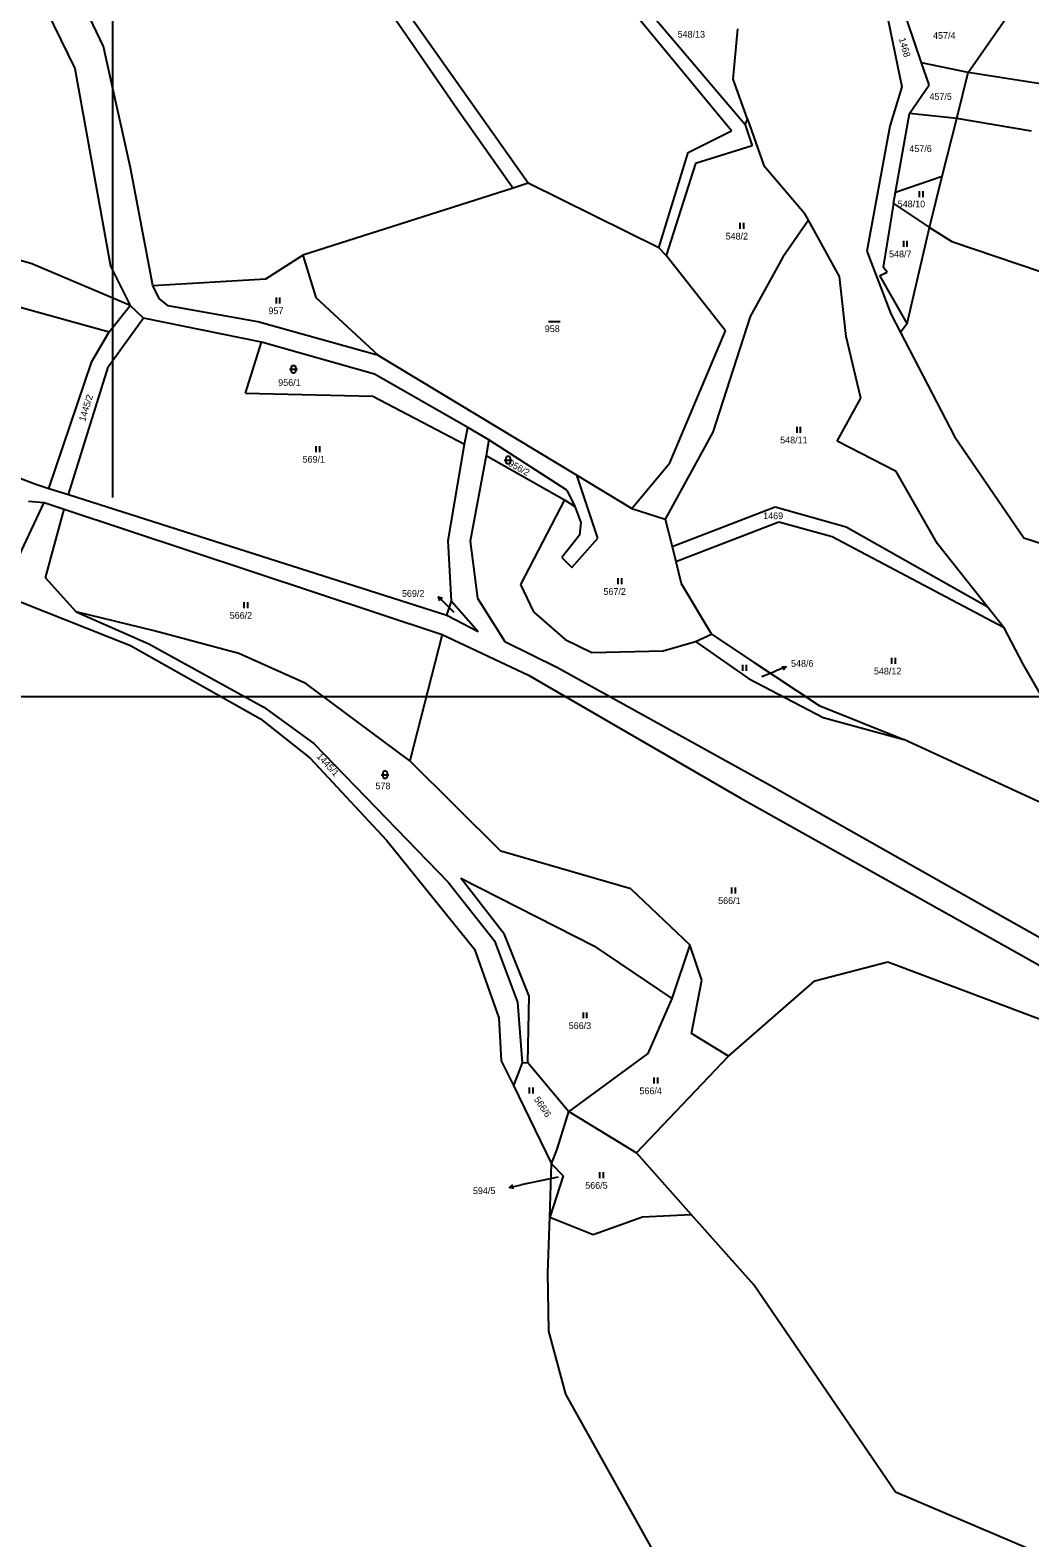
# Model space of a CAD drawing. Extents: x -852001 to -842497, y -1063614 to -1052182.
# Drawn here: x -848771 to -848517.5, y -1057263.9 to -1056881.4 of the extents above; entities that cross this region are included whole.
import ezdxf

# ---------------------------------------------------------------- set-up
doc = ezdxf.new("R2010")
doc.units = 0
for name, color, linetype in [('Default', 7, 'Continuous'), ('KLADY_ZMVM', 7, 'Continuous'), ('KN_HRANICE', 7, 'Continuous'), ('KN_KULTURY', 7, 'Continuous'), ('KN_PARCELY', 7, 'Continuous'), ('LEGENDA', 7, 'Continuous')]:
    doc.layers.add(name, color=color, linetype=linetype)

# ---------------------------------------------------------------- blocks, each defined once
blk = doc.blocks.new('306')
at = {"layer": 'Default'}
for p, q in [((-0.5, 1.5), (-0.5, 0)), ((0.5, 0), (0.5, 1.5))]:
    blk.add_line(p, q, dxfattribs=at)
blk = doc.blocks.new('316')
at = {"layer": 'Default'}
for points in [[(-1, 1), (0.27, 1), (1, 1)], [(-0.5, 1.5), (-0.4, 1.79), (-0.15, 1.97), (0.16, 1.97), (0.41, 1.79), (0.51, 1.5), (0.51, 0.5), (0.41, 0.21), (0.16, 0.03), (-0.15, 0.03), (-0.4, 0.21), (-0.5, 0.5), (-0.5, 1.5)]]:
    blk.add_lwpolyline(points, dxfattribs=at)
blk = doc.blocks.new('804')
at = {"layer": 'Default'}
blk.add_line((-1.5, 0), (1.5, 0), dxfattribs=at)
blk = doc.blocks.new('10292')
at = {"layer": 'Default'}
blk.add_line((0, 3), (0, 0), dxfattribs=at)
blk.add_lwpolyline([(-0.5, 2), (0, 3), (0.5, 2)], dxfattribs=at)

msp = doc.modelspace()

# ---------------------------------------------------------------- linework, layer by layer
at = {"layer": 'KLADY_ZMVM'}
msp.add_line((-848750, -1057000), (-848750, -1056500), dxfattribs=at)
at = {"layer": 'KN_HRANICE'}
for p, q in [((-848828.18, -1056749.16), (-848759.71, -1056891.14)), ((-848752.4, -1056885.52), (-848803.86, -1056777.8)), ((-848644.67, -1056920.2), (-848707.81, -1056830.91)), ((-848593.1, -1056906.95), (-848656.48, -1056830.13)), ((-848709.93, -1056832.61), (-848662.72, -1056901.35)), ((-848589.7, -1056905.37), (-848643.92, -1056841.44)), ((-848554.75, -1056872.56), (-848549.94, -1056895.74)), ((-848533.12, -1056892.09), (-848522.36, -1056876.75)), ((-848592.71, -1056893.78), (-848591.54, -1056881.04)), ((-848544.95, -1056889.68), (-848548.59, -1056878.97)), ((-848745.51, -1056916.29), (-848752.4, -1056885.52)), ((-848759.71, -1056891.14), (-848750.65, -1056941.27)), ((-848543.05, -1056895.26), (-848544.95, -1056889.68)), ((-848533.12, -1056892.09), (-848544.95, -1056889.68)), ((-848536, -1056903.82), (-848533.12, -1056892.09)), ((-848510.51, -1056895.7), (-848533.12, -1056892.09)), ((-848589.08, -1056904.01), (-848592.71, -1056893.78)), ((-848549.94, -1056895.74), (-848553, -1056905.72)), ((-848548.04, -1056902.53), (-848543.05, -1056895.26)), ((-848662.72, -1056901.35), (-848648.49, -1056921.48)), ((-848589.7, -1056905.37), (-848589.08, -1056904.01)), ((-848589.08, -1056904.01), (-848584.95, -1056915.69)), ((-848551.59, -1056922.52), (-848548.04, -1056902.53)), ((-848536, -1056903.82), (-848548.04, -1056902.53)), ((-848539.72, -1056918.46), (-848536, -1056903.82)), ((-848517.02, -1056907.05), (-848536, -1056903.82)), ((-848604.13, -1056912.41), (-848593.1, -1056906.95)), ((-848589.7, -1056905.37), (-848587.93, -1056910.75)), ((-848553, -1056905.72), (-848558.86, -1056937.48)), ((-848587.93, -1056910.75), (-848602.23, -1056915.24)), ((-848611.55, -1056936.6), (-848604.13, -1056912.41)), ((-848602.23, -1056915.24), (-848609.69, -1056938.54)), ((-848584.95, -1056915.69), (-848574.65, -1056927.8)), ((-848739.87, -1056946.18), (-848745.51, -1056916.29)), ((-848551.59, -1056922.52), (-848539.72, -1056918.46)), ((-848542.97, -1056931.46), (-848539.72, -1056918.46)), ((-848648.49, -1056921.48), (-848701.82, -1056938.46)), ((-848644.67, -1056920.2), (-848648.49, -1056921.48)), ((-848611.55, -1056936.6), (-848644.67, -1056920.2)), ((-848552.02, -1056925.36), (-848551.59, -1056922.52)), ((-848552.02, -1056925.36), (-848554.64, -1056941.54)), ((-848552.02, -1056925.36), (-848542.97, -1056931.46)), ((-848573.65, -1056929.62), (-848580.15, -1056938.95)), ((-848573.65, -1056929.62), (-848574.65, -1056927.8)), ((-848565.78, -1056943.93), (-848573.65, -1056929.62)), ((-848548.58, -1056955.83), (-848542.97, -1056931.46)), ((-848542.97, -1056931.46), (-848537.27, -1056935.01)), ((-848537.27, -1056935.01), (-848500.98, -1056947.31)), ((-848770.6, -1056940.69), (-848784.91, -1056936.55)), ((-848711.24, -1056944.47), (-848701.82, -1056938.46)), ((-848701.82, -1056938.46), (-848698.56, -1056949.2)), ((-848609.69, -1056938.54), (-848611.55, -1056936.6)), ((-848594.67, -1056957.65), (-848609.69, -1056938.54)), ((-848558.86, -1056937.48), (-848552.74, -1056953.4)), ((-848745.67, -1056951.27), (-848770.6, -1056940.69)), ((-848750.65, -1056941.27), (-848745.67, -1056951.27)), ((-848580.15, -1056938.95), (-848588.38, -1056954.07)), ((-848553.69, -1056942.78), (-848554.64, -1056941.54)), ((-848798.55, -1056944.74), (-848750.93, -1056957.95)), ((-848739.87, -1056946.18), (-848711.24, -1056944.47)), ((-848738.3, -1056949.45), (-848739.87, -1056946.18)), ((-848564.06, -1056959.08), (-848565.78, -1056943.93)), ((-848555.53, -1056943.66), (-848553.69, -1056942.78)), ((-848548.58, -1056955.83), (-848555.53, -1056943.66)), ((-848735.99, -1056951.35), (-848738.3, -1056949.45)), ((-848698.56, -1056949.2), (-848682.69, -1056963.91)), ((-848750.93, -1056957.95), (-848745.67, -1056951.27)), ((-848742.29, -1056954.46), (-848745.67, -1056951.27)), ((-848713.26, -1056955.43), (-848735.99, -1056951.35)), ((-848588.38, -1056954.07), (-848597.91, -1056983.38)), ((-848552.74, -1056953.4), (-848550.28, -1056958.12)), ((-848755.32, -1056965.44), (-848750.93, -1056957.95)), ((-848742.29, -1056954.46), (-848751.21, -1056966.93)), ((-848712.37, -1056960.52), (-848742.29, -1056954.46)), ((-848682.69, -1056963.91), (-848713.26, -1056955.43)), ((-848608.75, -1056991.15), (-848594.67, -1056957.65)), ((-848548.58, -1056955.83), (-848550.28, -1056958.12)), ((-848716.35, -1056973.49), (-848712.37, -1056960.52)), ((-848683.64, -1056968.67), (-848712.37, -1056960.52)), ((-848560.31, -1056974.75), (-848564.06, -1056959.08)), ((-848550.28, -1056958.12), (-848536.56, -1056984.46)), ((-848766.22, -1056997.65), (-848755.32, -1056965.44)), ((-848682.69, -1056963.91), (-848632.4, -1056994.3)), ((-848761.29, -1056999.22), (-848751.21, -1056966.93)), ((-848660.01, -1056982.18), (-848683.64, -1056968.67)), ((-848716.35, -1056973.49), (-848684.09, -1056974.22)), ((-848684.09, -1056974.22), (-848660.81, -1056986.46)), ((-848566.34, -1056985.65), (-848560.31, -1056974.75)), ((-848660.81, -1056986.46), (-848660.01, -1056982.18)), ((-848654.7, -1056985.34), (-848660.01, -1056982.18)), ((-848597.91, -1056983.38), (-848609.93, -1057005.5)), ((-848536.56, -1056984.46), (-848518.98, -1057010.18)), ((-848794.78, -1056987.07), (-848769.55, -1056996.59)), ((-848665, -1057010.87), (-848660.81, -1056986.46)), ((-848654.7, -1056985.34), (-848655.36, -1056989.32)), ((-848634.94, -1056998.1), (-848654.7, -1056985.34)), ((-848551.36, -1056993.36), (-848566.34, -1056985.65)), ((-848655.36, -1056989.32), (-848659.41, -1057011.08)), ((-848655.36, -1056989.32), (-848635.5, -1057000.56)), ((-848618.39, -1057002.77), (-848608.75, -1056991.15)), ((-848627, -1057010.3), (-848632.4, -1056994.3)), ((-848632.4, -1056994.3), (-848618.39, -1057002.77)), ((-848540.94, -1057011.71), (-848551.36, -1056993.36)), ((-848769.55, -1056996.59), (-848766.22, -1056997.65)), ((-848766.22, -1056997.65), (-848761.29, -1056999.22)), ((-848761.29, -1056999.22), (-848665.36, -1057029.84)), ((-848634.94, -1056998.1), (-848632.88, -1057002.25)), ((-848778.33, -1057024.53), (-848767.43, -1057001.23)), ((-848771.39, -1057000.87), (-848767.43, -1057001.23)), ((-848767.43, -1057001.23), (-848762.41, -1057002.9)), ((-848767.14, -1057020.35), (-848762.41, -1057002.9)), ((-848762.41, -1057002.9), (-848666.55, -1057034.72)), ((-848635.5, -1057000.56), (-848646.62, -1057022.01)), ((-848635.5, -1057000.56), (-848632.88, -1057002.25)), ((-848632.88, -1057002.25), (-848631.39, -1057006.3)), ((-848618.39, -1057002.77), (-848609.93, -1057005.5)), ((-848608.2, -1057012.41), (-848582.08, -1057002.37)), ((-848582.08, -1057002.37), (-848564.05, -1057007.39)), ((-848631.39, -1057006.3), (-848631.65, -1057009.52)), ((-848609.93, -1057005.5), (-848608.2, -1057012.41)), ((-848607.26, -1057016.19), (-848581.12, -1057006.16)), ((-848581.12, -1057006.16), (-848567.65, -1057009.9)), ((-848564.05, -1057007.39), (-848528.32, -1057027.61)), ((-848664.18, -1057026.28), (-848665, -1057010.87)), ((-848659.41, -1057011.08), (-848657.54, -1057025.49)), ((-848631.65, -1057009.52), (-848636.17, -1057015.22)), ((-848633.64, -1057017.74), (-848627, -1057010.3)), ((-848567.65, -1057009.9), (-848524.15, -1057032.85)), ((-848518.98, -1057010.18), (-848490.15, -1057019.65)), ((-848636.17, -1057015.22), (-848633.64, -1057017.74)), ((-848608.2, -1057012.41), (-848607.26, -1057016.19)), ((-848528.32, -1057027.61), (-848540.94, -1057011.71)), ((-848607.26, -1057016.19), (-848605.87, -1057021.77)), ((-848759.37, -1057028.94), (-848767.14, -1057020.35)), ((-848646.62, -1057022.01), (-848643.39, -1057028.94)), ((-848605.87, -1057021.77), (-848598.19, -1057034.62)), ((-848778.33, -1057024.53), (-848745.58, -1057037.48)), ((-848665.36, -1057029.84), (-848664.18, -1057026.28)), ((-848664.18, -1057026.28), (-848657.39, -1057033.96)), ((-848657.54, -1057025.49), (-848650.58, -1057036.5)), ((-848739.51, -1057033.84), (-848759.37, -1057028.94)), ((-848759.37, -1057028.94), (-848740.87, -1057037.09)), ((-848665.36, -1057029.84), (-848657.39, -1057033.96)), ((-848643.39, -1057028.94), (-848635.31, -1057035.97)), ((-848524.15, -1057032.85), (-848528.32, -1057027.61)), ((-848718.12, -1057039.57), (-848739.51, -1057033.84)), ((-848524.15, -1057032.85), (-848519.3, -1057042.27)), ((-848745.58, -1057037.48), (-848712.55, -1057056.16)), ((-848740.87, -1057037.09), (-848711.76, -1057053.2)), ((-848666.55, -1057034.72), (-848674.74, -1057066.75)), ((-848666.55, -1057034.72), (-848644.58, -1057045.04)), ((-848650.58, -1057036.5), (-848637.23, -1057043.14)), ((-848635.31, -1057035.97), (-848628.56, -1057039.29)), ((-848610.5, -1057038.91), (-848602.23, -1057036.54)), ((-848602.23, -1057036.54), (-848598.19, -1057034.62)), ((-848602.23, -1057036.54), (-848588.84, -1057045.91)), ((-848598.19, -1057034.62), (-848587.4, -1057041.85)), ((-848701.08, -1057047.2), (-848718.12, -1057039.57)), ((-848628.56, -1057039.29), (-848610.5, -1057038.91)), ((-848587.4, -1057041.85), (-848570.95, -1057052.77)), ((-848644.58, -1057045.04), (-848590.96, -1057076.16)), ((-848637.23, -1057043.14), (-848582.77, -1057073.32)), ((-848588.84, -1057045.91), (-848569.86, -1057055.81)), ((-848519.3, -1057042.27), (-848503.9, -1057068.91)), ((-848674.74, -1057066.75), (-848701.08, -1057047.2)), ((-848711.76, -1057053.2), (-848699.04, -1057062.35)), ((-848570.95, -1057052.77), (-848549.47, -1057061.41)), ((-848712.55, -1057056.16), (-848700, -1057066.07)), ((-848569.86, -1057055.81), (-848549.47, -1057061.41)), ((-848699.04, -1057062.35), (-848665.03, -1057097.59)), ((-848506.04, -1057081.45), (-848549.47, -1057061.41)), ((-848700, -1057066.07), (-848680.65, -1057086.9)), ((-848651.66, -1057089.67), (-848674.74, -1057066.75)), ((-848590.96, -1057076.16), (-848523.24, -1057114.03)), ((-848582.77, -1057073.32), (-848530.27, -1057102.96)), ((-848680.65, -1057086.9), (-848658.34, -1057114.58)), ((-848618.65, -1057099.29), (-848651.66, -1057089.67)), ((-848665.03, -1057097.59), (-848653.27, -1057112.43)), ((-848661.79, -1057096.58), (-848628.06, -1057113.7)), ((-848650.73, -1057110.83), (-848661.79, -1057096.58)), ((-848618.65, -1057099.29), (-848603.68, -1057113.45)), ((-848530.27, -1057102.96), (-848441.09, -1057153.24)), ((-848644.47, -1057126.51), (-848650.73, -1057110.83)), ((-848658.34, -1057114.58), (-848652.18, -1057131.97)), ((-848653.27, -1057112.43), (-848647.43, -1057127.98)), ((-848628.06, -1057113.7), (-848608.29, -1057127.07)), ((-848603.68, -1057113.45), (-848608.29, -1057127.07)), ((-848600.64, -1057122.44), (-848603.68, -1057113.45)), ((-848523.24, -1057114.03), (-848433.37, -1057164.99)), ((-848572.02, -1057122.57), (-848553.53, -1057117.8)), ((-848553.53, -1057117.8), (-848506.45, -1057135.5)), ((-848603.3, -1057135.98), (-848600.64, -1057122.44)), ((-848593.92, -1057141.68), (-848572.02, -1057122.57)), ((-848647.43, -1057127.98), (-848646.22, -1057143.44)), ((-848644.75, -1057143.32), (-848644.47, -1057126.51)), ((-848608.29, -1057127.07), (-848614.37, -1057141.03)), ((-848652.18, -1057131.97), (-848651.54, -1057142.88)), ((-848593.92, -1057141.68), (-848603.3, -1057135.98)), ((-848614.37, -1057141.03), (-848634.36, -1057155.73)), ((-848617.25, -1057166.23), (-848593.92, -1057141.68)), ((-848651.54, -1057142.88), (-848648.42, -1057149.2)), ((-848646.22, -1057143.44), (-848648.42, -1057149.2)), ((-848646.22, -1057143.44), (-848644.75, -1057143.32)), ((-848644.75, -1057143.32), (-848634.36, -1057155.73)), ((-848648.42, -1057149.2), (-848638.76, -1057169.08)), ((-848637.31, -1057165.36), (-848634.36, -1057155.73)), ((-848634.36, -1057155.73), (-848617.25, -1057166.23)), ((-848638.76, -1057169.08), (-848637.31, -1057165.36)), ((-848603.33, -1057181.93), (-848617.25, -1057166.23)), ((-848639.17, -1057182.56), (-848638.76, -1057169.08)), ((-848635.87, -1057172.06), (-848639.17, -1057182.56)), ((-848638.76, -1057169.08), (-848635.87, -1057172.06)), ((-848639.68, -1057196.73), (-848639.17, -1057182.56)), ((-848639.17, -1057182.56), (-848628.26, -1057186.98)), ((-848628.26, -1057186.98), (-848615.7, -1057182.46)), ((-848615.7, -1057182.46), (-848603.33, -1057181.93)), ((-848587.49, -1057199.78), (-848603.33, -1057181.93)), ((-848639.43, -1057211.54), (-848639.68, -1057196.73)), ((-848551.54, -1057252.34), (-848587.49, -1057199.78)), ((-848635.12, -1057227.49), (-848639.43, -1057211.54)), ((-848606.85, -1057278.11), (-848635.12, -1057227.49)), ((-848517.95, -1057266.66), (-848551.54, -1057252.34))]:
    msp.add_line(p, q, dxfattribs=at)
at = {"layer": 'KN_PARCELY'}
for p, q in [((-848663.51, -1057029.13), (-848665.35, -1057027.29)), ((-848585.43, -1057045.4), (-848582.06, -1057044.04)), ((-848637.09, -1057172.46), (-848646.52, -1057174.4))]:
    msp.add_line(p, q, dxfattribs=at)
at = {"layer": 'LEGENDA'}
msp.add_lwpolyline([(-848910.31, -1057050.45), (-848316.31, -1057050.45), (-848316.31, -1056630.45), (-848910.31, -1056630.45)], close=True, dxfattribs=at)

# ---------------------------------------------------------------- block references
at = {"layer": 'KN_KULTURY'}
for name, p in [('306', (-848545.05, -1056923.72)), ('306', (-848590.51, -1056931.81)), ('306', (-848549.05, -1056936.34)), ('306', (-848708.14, -1056950.74)), ('804', (-848638.06, -1056955.3)), ('316', (-848704.2, -1056968.41)), ('306', (-848576.1, -1056983.53)), ('306', (-848698.02, -1056988.43)), ('316', (-848649.8, -1056991.46)), ('306', (-848621.48, -1057021.97)), ('306', (-848716.27, -1057028.03)), ('306', (-848552.08, -1057042.17)), ('306', (-848589.83, -1057043.93)), ('316', (-848681, -1057071.3)), ('306', (-848592.64, -1057100.41)), ('306', (-848630.29, -1057132.12)), ('306', (-848612.31, -1057148.67)), ('306', (-848643.92, -1057151.17)), ('306', (-848626.1, -1057172.66))]:
    msp.add_blockref(name, p, dxfattribs=at)
at = {"layer": 'KN_PARCELY'}
for p, rotation in [((-848665.35, -1057027.29), 44.977187), ((-848582.06, -1057044.04), -68.020708), ((-848646.52, -1057174.4), 101.64271300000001)]:
    msp.add_blockref('10292', p, dxfattribs=dict(at, rotation=rotation))

# ---------------------------------------------------------------- texts
for s, height, p in [('548/13', 1.7, (-848606.81, -1056883.28)), ('457/4', 1.7, (-848542.03, -1056883.59)), ('457/5', 1.7, (-848542.94, -1056899.08)), ('457/6', 1.7, (-848548.05, -1056912.31)), ('548/10', 1.7, (-848550.99, -1056926.33)), ('548/2', 1.7, (-848594.64, -1056934.51)), ('548/7', 1.7, (-848553.18, -1056939.04)), ('957', 1.7, (-848710.57, -1056953.44)), ('958', 1.7, (-848640.49, -1056958)), ('956/1', 1.7, (-848708.09, -1056971.65)), ('548/11', 1.7, (-848580.8, -1056986.23)), ('569/1', 1.7, (-848701.91, -1056991.13)), ('1469', 1.7, (-848585.1, -1057005.46)), ('567/2', 1.7, (-848625.61, -1057024.67)), ('569/2', 1.7, (-848676.72, -1057025.17)), ('566/2', 1.7, (-848720.4, -1057030.73)), ('569/2', 0.1, (-848663.75, -1057029.13)), ('548/6', 1.7, (-848578.04, -1057042.92)), ('548/6', 0.1, (-848585.67, -1057045.4)), ('548/12', 1.7, (-848557.02, -1057044.87)), ('578', 1.7, (-848683.43, -1057074)), ('566/1', 1.7, (-848596.53, -1057103.11)), ('566/3', 1.7, (-848634.42, -1057134.82)), ('566/4', 1.7, (-848616.48, -1057151.37)), ('594/5', 1.7, (-848658.71, -1057176.71)), ('594/5', 0.1, (-848637.33, -1057172.46)), ('566/5', 1.7, (-848630.23, -1057175.36))]:
    msp.add_text(s, height=height, dxfattribs=at).set_placement(p)
for s, rotation, p in [('1468', 285.734, (-848550.7, -1056883.56)), ('1445/2', 72.88, (-848757.07, -1056980.8)), ('956/2', 330.826, (-848649.91, -1056991.79)), ('1445/1', 313.064, (-848698.49, -1057065.79)), ('566/6', 303.668, (-848643.32, -1057152.68))]:
    msp.add_text(s, height=1.7, rotation=rotation, dxfattribs=at).set_placement(p)

doc.saveas('drawing.dxf')
